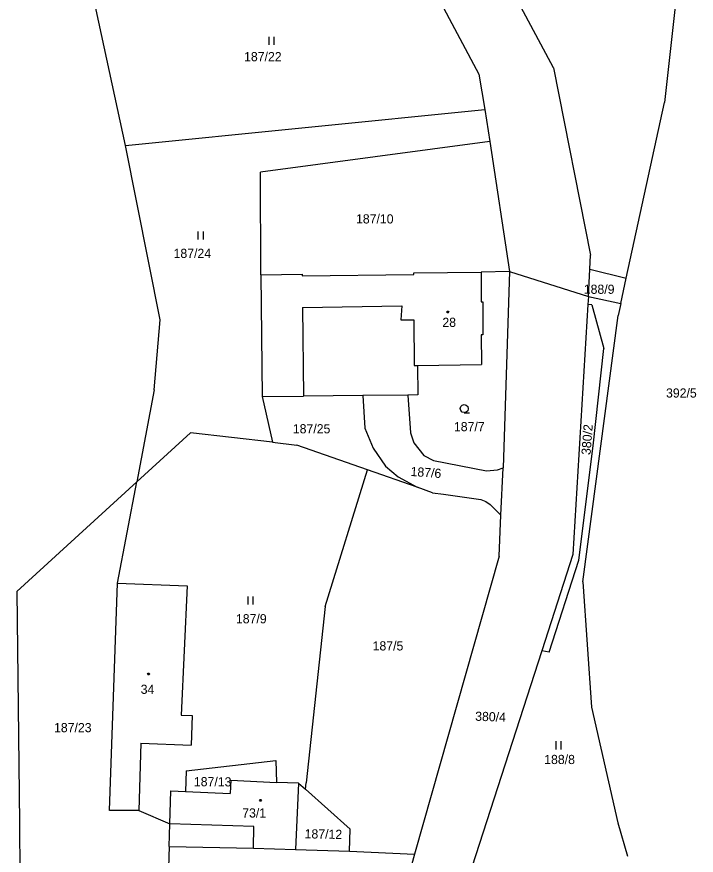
# Model space of a CAD drawing. Extents: x -811039 to -805820, y -1161436 to -1155864.
# Drawn here: x -806673 to -806547.2, y -1157883.1 to -1157727.6 of the extents above; entities that cross this region are included whole.
import ezdxf

# ---------------------------------------------------------------- set-up
doc = ezdxf.new("R2010")
doc.units = 0
for name, color, linetype in [('Default', 7, 'Continuous'), ('KN_HRANICE', 7, 'Continuous'), ('KN_KULTURY', 7, 'Continuous'), ('KN_PARCELY', 7, 'Continuous'), ('KN_SLUCKY', 7, 'Continuous')]:
    doc.layers.add(name, color=color, linetype=linetype)

# ---------------------------------------------------------------- blocks, each defined once
blk = doc.blocks.new('304')
at = {"layer": 'Default'}
blk.add_lwpolyline([(0, 0), (-0.38, 0.1), (-0.65, 0.37), (-0.75, 0.74), (-0.65, 1.11), (-0.38, 1.38), (-0.01, 1.48), (0.36, 1.38), (0.63, 1.11), (0.73, 0.73), (0.63, 0.35), (0.36, 0.08), (-0.02, -0.02), (0.98, -0.02)], dxfattribs=at)
blk = doc.blocks.new('306')
at = {"layer": 'Default'}
for p, q in [((-0.5, 1.5), (-0.5, 0)), ((0.5, 0), (0.5, 1.5))]:
    blk.add_line(p, q, dxfattribs=at)
blk = doc.blocks.new('402')
at = {"layer": 'Default'}
blk.add_lwpolyline([(0.09, 0.15), (0.18, 0), (0.09, -0.15), (-0.09, -0.15), (-0.18, 0), (-0.09, 0.15), (0.09, 0.15)], dxfattribs=at)

msp = doc.modelspace()

# ---------------------------------------------------------------- linework, layer by layer
at = {"layer": 'KN_HRANICE'}
for p, q in [((-806573.63, -1157737.11), (-806605.65, -1157676.97)), ((-806549.38, -1157710.12), (-806553.08, -1157743.51)), ((-806598.27, -1157717.88), (-806587.43, -1157738.28)), ((-806652.88, -1157751.49), (-806658.86, -1157723.93)), ((-806573.63, -1157737.11), (-806566.78, -1157771.82)), ((-806587.43, -1157738.28), (-806586.37, -1157744.82)), ((-806560.15, -1157776.09), (-806553.08, -1157743.51)), ((-806652.88, -1157751.49), (-806586.37, -1157744.82)), ((-806586.37, -1157744.82), (-806585.4, -1157750.78)), ((-806646.47, -1157783.84), (-806652.88, -1157751.49)), ((-806585.4, -1157750.78), (-806627.9, -1157756.44)), ((-806585.4, -1157750.78), (-806581.76, -1157774.87)), ((-806627.81, -1157775.49), (-806627.9, -1157756.44)), ((-806566.87, -1157774.43), (-806566.78, -1157771.82)), ((-806599.49, -1157775.1), (-806587.01, -1157774.97)), ((-806587.01, -1157774.97), (-806587.04, -1157780.48)), ((-806581.76, -1157774.87), (-806587.01, -1157774.97)), ((-806581.76, -1157774.87), (-806582.95, -1157811.26)), ((-806581.76, -1157774.87), (-806567.16, -1157779.47)), ((-806567.16, -1157779.47), (-806566.87, -1157774.43)), ((-806566.87, -1157774.43), (-806560.15, -1157776.09)), ((-806627.81, -1157775.49), (-806620.17, -1157775.36)), ((-806627.81, -1157775.49), (-806627.56, -1157798.04)), ((-806620.17, -1157775.36), (-806620.17, -1157775.65)), ((-806620.17, -1157775.65), (-806599.49, -1157775.4)), ((-806599.49, -1157775.4), (-806599.49, -1157775.1)), ((-806561.17, -1157780.8), (-806560.15, -1157776.09)), ((-806567.16, -1157779.47), (-806567.25, -1157780.95)), ((-806567.16, -1157779.47), (-806561.17, -1157780.8)), ((-806587.04, -1157780.48), (-806586.72, -1157780.47)), ((-806586.72, -1157780.47), (-806586.69, -1157786.6)), ((-806567.25, -1157780.95), (-806570.03, -1157827.34)), ((-806566.51, -1157781.05), (-806567.25, -1157780.95)), ((-806566.51, -1157781.05), (-806564.32, -1157789.13)), ((-806561.17, -1157780.8), (-806561.66, -1157782.99)), ((-806647.62, -1157796.82), (-806646.47, -1157783.84)), ((-806568.2, -1157832.4), (-806561.66, -1157782.99)), ((-806586.69, -1157786.6), (-806587.01, -1157786.62)), ((-806587.01, -1157786.62), (-806586.98, -1157792.11)), ((-806566.3, -1157807.17), (-806564.32, -1157789.13)), ((-806598.84, -1157792.26), (-806586.98, -1157792.11)), ((-806598.84, -1157792.26), (-806598.77, -1157797.7)), ((-806647.62, -1157796.82), (-806650.83, -1157813.86)), ((-806627.56, -1157798.04), (-806619.95, -1157797.95)), ((-806627.56, -1157798.04), (-806625.69, -1157806.51)), ((-806608.95, -1157797.84), (-806619.95, -1157797.95)), ((-806600.61, -1157797.78), (-806608.95, -1157797.84)), ((-806608.95, -1157797.84), (-806608.59, -1157803.89)), ((-806598.77, -1157797.7), (-806600.61, -1157797.78)), ((-806600.61, -1157797.78), (-806600.12, -1157804.74)), ((-806608.59, -1157803.89), (-806607.06, -1157807.61)), ((-806640.85, -1157804.79), (-806650.83, -1157813.86)), ((-806625.69, -1157806.51), (-806640.85, -1157804.79)), ((-806600.12, -1157804.74), (-806599.47, -1157806.63)), ((-806625.69, -1157806.51), (-806621.19, -1157807.02)), ((-806608.1, -1157811.62), (-806621.19, -1157807.02)), ((-806607.06, -1157807.61), (-806604.74, -1157810.94)), ((-806599.47, -1157806.63), (-806597.66, -1157808.95)), ((-806568.91, -1157828.39), (-806566.3, -1157807.17)), ((-806597.66, -1157808.95), (-806595.83, -1157809.92)), ((-806595.83, -1157809.92), (-806586.05, -1157811.78)), ((-806615.94, -1157836.95), (-806608.1, -1157811.62)), ((-806598.89, -1157814.86), (-806608.1, -1157811.62)), ((-806604.74, -1157810.94), (-806602.37, -1157812.91)), ((-806586.05, -1157811.78), (-806584.01, -1157811.65)), ((-806584.01, -1157811.65), (-806582.95, -1157811.26)), ((-806583.38, -1157820), (-806582.95, -1157811.26)), ((-806650.83, -1157813.86), (-806673.04, -1157834.14)), ((-806654.38, -1157832.63), (-806650.83, -1157813.86)), ((-806602.37, -1157812.91), (-806598.89, -1157814.86)), ((-806596.03, -1157815.9), (-806598.89, -1157814.86)), ((-806596.03, -1157815.9), (-806593.99, -1157816.14)), ((-806593.99, -1157816.14), (-806587.09, -1157817.14)), ((-806587.09, -1157817.14), (-806586.15, -1157817.46)), ((-806586.15, -1157817.46), (-806585.36, -1157818.07)), ((-806585.36, -1157818.07), (-806584.65, -1157818.76)), ((-806584.65, -1157818.76), (-806583.38, -1157820)), ((-806583.67, -1157827.65), (-806583.38, -1157820)), ((-806583.67, -1157827.65), (-806599.35, -1157882.87)), ((-806570.03, -1157827.34), (-806575.79, -1157845.15)), ((-806574.44, -1157845.44), (-806568.91, -1157828.39)), ((-806568.2, -1157832.4), (-806566.58, -1157855.63)), ((-806655.88, -1157874.75), (-806654.38, -1157832.63)), ((-806654.38, -1157832.63), (-806641.47, -1157833.11)), ((-806641.47, -1157833.11), (-806642.59, -1157857.11)), ((-806673.04, -1157834.14), (-806672.55, -1157877.06)), ((-806615.94, -1157836.95), (-806619.47, -1157869.66)), ((-806575.79, -1157845.15), (-806588.75, -1157885.25)), ((-806574.44, -1157845.44), (-806575.79, -1157845.15)), ((-806566.58, -1157855.63), (-806561.71, -1157877.02)), ((-806642.59, -1157857.11), (-806640.53, -1157857.18)), ((-806640.53, -1157857.18), (-806640.73, -1157862.64)), ((-806650.07, -1157862.3), (-806650.43, -1157874.79)), ((-806650.07, -1157862.3), (-806640.73, -1157862.64)), ((-806641.64, -1157867.42), (-806625.04, -1157865.47)), ((-806625.04, -1157865.47), (-806624.95, -1157869.54)), ((-806641.64, -1157867.42), (-806641.77, -1157871.21)), ((-806633.39, -1157869.12), (-806633.51, -1157871.6)), ((-806633.39, -1157869.12), (-806624.95, -1157869.54)), ((-806620.84, -1157869.67), (-806624.95, -1157869.54)), ((-806620.84, -1157869.67), (-806621.39, -1157881.98)), ((-806620.84, -1157869.67), (-806619.59, -1157870.79)), ((-806619.59, -1157870.79), (-806619.47, -1157869.66)), ((-806644.69, -1157877.22), (-806644.5, -1157871.11)), ((-806644.5, -1157871.11), (-806641.77, -1157871.21)), ((-806641.77, -1157871.21), (-806633.51, -1157871.6)), ((-806619.59, -1157870.79), (-806611.32, -1157878.24)), ((-806650.43, -1157874.79), (-806655.88, -1157874.75)), ((-806650.43, -1157874.79), (-806644.69, -1157877.22)), ((-806672.55, -1157877.06), (-806672.48, -1157889.17)), ((-806644.79, -1157881.45), (-806644.69, -1157877.22)), ((-806561.71, -1157877.02), (-806559.95, -1157883.23)), ((-806611.42, -1157882.28), (-806611.32, -1157878.24)), ((-806644.79, -1157881.45), (-806644.96, -1157885.34)), ((-806644.79, -1157881.45), (-806629.22, -1157881.72)), ((-806629.22, -1157881.72), (-806621.39, -1157881.98)), ((-806621.39, -1157881.98), (-806611.42, -1157882.28)), ((-806611.42, -1157882.28), (-806599.35, -1157882.87)), ((-806599.35, -1157882.87), (-806603.42, -1157897.19))]:
    msp.add_line(p, q, dxfattribs=at)
at = {"layer": 'KN_SLUCKY'}
for p, q in [((-806620.14, -1157781.52), (-806601.73, -1157781.21)), ((-806601.73, -1157781.21), (-806601.91, -1157783.85)), ((-806620.14, -1157781.52), (-806619.95, -1157797.95)), ((-806601.91, -1157783.85), (-806599.51, -1157783.79)), ((-806599.51, -1157783.79), (-806599.41, -1157792.27)), ((-806599.41, -1157792.27), (-806598.84, -1157792.26)), ((-806629.11, -1157877.75), (-806644.69, -1157877.22)), ((-806629.22, -1157881.72), (-806629.11, -1157877.75))]:
    msp.add_line(p, q, dxfattribs=at)

# ---------------------------------------------------------------- block references
at = {"layer": 'KN_KULTURY'}
for name, p in [('306', (-806625.85, -1157732.87)), ('306', (-806638.98, -1157768.94)), ('402', (-806593.21, -1157782.38)), ('304', (-806590.14, -1157801.02)), ('306', (-806629.76, -1157836.57)), ('402', (-806648.63, -1157849.48)), ('306', (-806572.71, -1157863.44)), ('402', (-806627.9, -1157872.87))]:
    msp.add_blockref(name, p, dxfattribs=at)

# ---------------------------------------------------------------- texts
at = {"layer": 'KN_PARCELY'}
for s, p in [('187/22', (-806630.94, -1157735.89)), ('187/10', (-806610.21, -1157765.96)), ('187/24', (-806644, -1157772.35)), ('188/9', (-806568.02, -1157779)), ('28', (-806594.21, -1157785.13)), ('392/5', (-806552.79, -1157798.23)), ('187/7', (-806592.07, -1157804.47)), ('187/25', (-806621.91, -1157804.86)), ('187/9', (-806632.45, -1157840.07)), ('187/5', (-806607.13, -1157845.1)), ('34', (-806650.09, -1157853.14)), ('187/23', (-806666.14, -1157860.25)), ('188/8', (-806575.35, -1157866.15)), ('73/1', (-806631.28, -1157876.06))]:
    msp.add_text(s, height=1.7, dxfattribs=at).set_placement(p)
for s, rotation, p in [('380/2', 85.6, (-806566.78, -1157808.91)), ('187/6', 355.979, (-806600.15, -1157812.75)), ('380/4', 357.984, (-806588.16, -1157858.12)), ('187/13', 359.646, (-806640.24, -1157870.26)), ('187/12', 358.901, (-806619.74, -1157879.91))]:
    msp.add_text(s, height=1.7, rotation=rotation, dxfattribs=at).set_placement(p)

doc.saveas('drawing.dxf')
